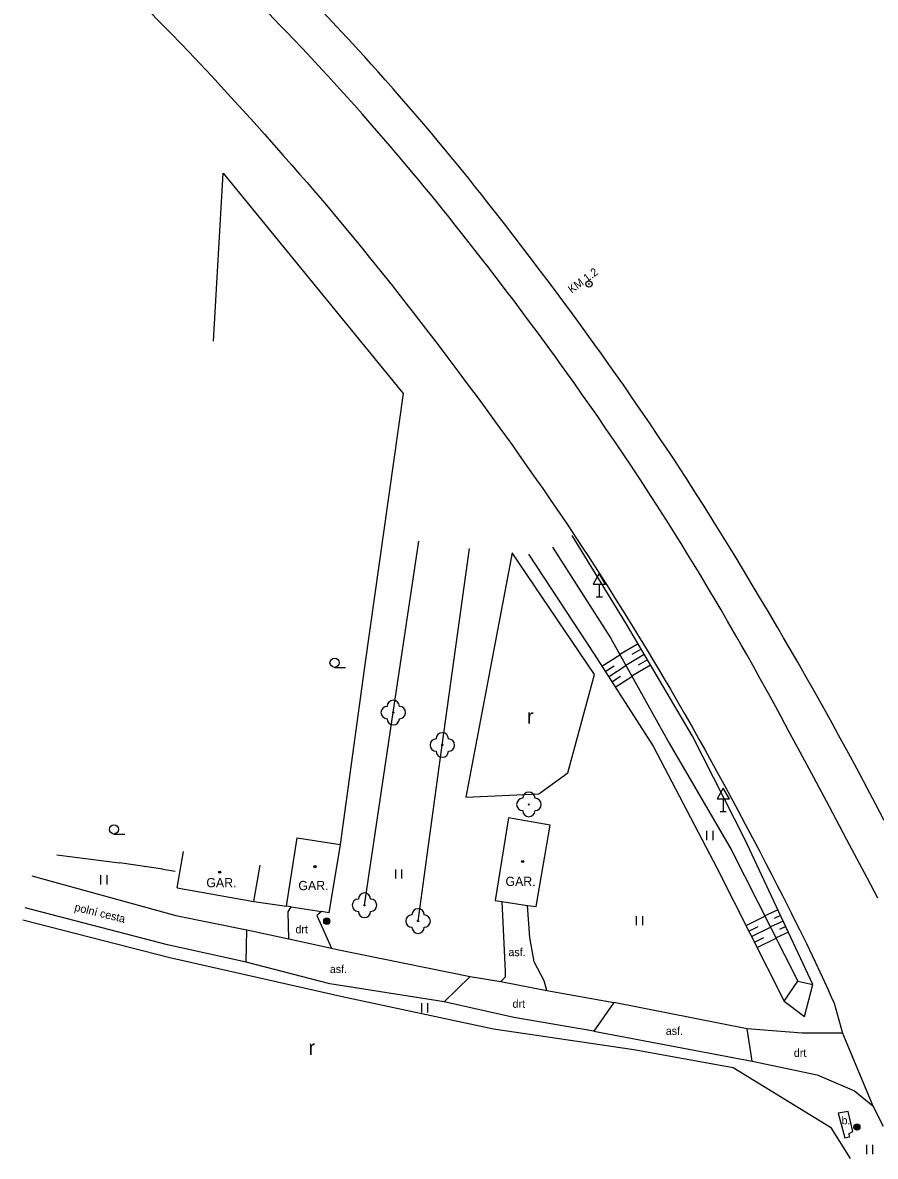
# Model space of a CAD drawing. Extents: x -539244 to -537359, y -1183785 to -1181851.
# Drawn here: x -538628.7 to -538559.5, y -1183406.5 to -1183314.4 of the extents above; entities that cross this region are included whole.
import ezdxf

# ---------------------------------------------------------------- set-up
doc = ezdxf.new("R2010")
doc.units = 0
for name, color, linetype in [('Vrstva 10', 7, 'Continuous'), ('Vrstva 11', 7, 'Continuous'), ('Vrstva 13', 7, 'Continuous'), ('Vrstva 14', 7, 'Continuous'), ('Vrstva 15', 7, 'Continuous'), ('Vrstva 21', 7, 'Continuous'), ('Vrstva 22', 7, 'Continuous'), ('Vrstva 23', 7, 'Continuous'), ('Vrstva 25', 7, 'Continuous'), ('Vrstva 34', 7, 'Continuous'), ('Vrstva 36', 7, 'Continuous'), ('Vrstva 39', 7, 'Continuous'), ('Vrstva 40', 7, 'Continuous'), ('Vrstva 41', 7, 'Continuous'), ('Vrstva 5', 7, 'Continuous'), ('Vrstva 6', 7, 'Continuous'), ('Vrstva 7', 7, 'Continuous'), ('Vrstva 8', 7, 'Continuous')]:
    doc.layers.add(name, color=color, linetype=linetype)

msp = doc.modelspace()

# ---------------------------------------------------------------- linework, layer by layer
at = {"layer": 'Vrstva 10'}
for p, q in [((-538600.501, -1183322.527), (-538601.165, -1183321.773)), ((-538609.088, -1183323.418), (-538608.299, -1183324.305)), ((-538602.366, -1183331.225), (-538601.676, -1183332.061)), ((-538586.793, -1183339.695), (-538587.56, -1183338.659)), ((-538595.932, -1183339.308), (-538594.993, -1183340.538)), ((-538580.591, -1183348.465), (-538581.331, -1183347.379)), ((-538575.254, -1183356.683), (-538575.765, -1183355.863)), ((-538572.192, -1183375.483), (-538571.651, -1183376.476)), ((-538563.219, -1183378.053), (-538564.475, -1183375.691)), ((-538567.032, -1183385.26), (-538566.647, -1183386.018)), ((-538562.16, -1183396.46), (-538559.68, -1183402.36)), ((-538559.68, -1183402.36), (-538558.86, -1183403.993))]:
    msp.add_line(p, q, dxfattribs=at)
for points in [[(-538607.834, -1183314.562), (-538608.751, -1183313.619), (-538609.443, -1183312.915), (-538609.964, -1183312.389), (-538610.75, -1183311.603), (-538611.54, -1183310.82), (-538612.321, -1183310.053), (-538613.079, -1183309.313), (-538613.815, -1183308.599), (-538614.53, -1183307.91)], [(-538621.887, -1183310.038), (-538621.344, -1183310.564), (-538620.837, -1183311.06), (-538619.891, -1183311.993), (-538619.066, -1183312.814), (-538618.348, -1183313.536), (-538617.722, -1183314.171), (-538617.176, -1183314.728), (-538616.7, -1183315.218), (-538615.869, -1183316.078), (-538615.249, -1183316.727)], [(-538601.165, -1183321.773), (-538601.79, -1183321.069), (-538602.378, -1183320.412), (-538602.933, -1183319.798), (-538603.455, -1183319.224), (-538603.946, -1183318.687), (-538604.408, -1183318.185), (-538605.279, -1183317.249), (-538606.045, -1183316.433), (-538606.72, -1183315.722), (-538607.313, -1183315.102), (-538607.834, -1183314.562)], [(-538615.249, -1183316.727), (-538614.322, -1183317.705), (-538613.4, -1183318.69), (-538612.858, -1183319.273), (-538611.814, -1183320.407), (-538610.84, -1183321.473), (-538609.933, -1183322.475), (-538609.088, -1183323.418)], [(-538594.637, -1183329.503), (-538595.133, -1183328.89), (-538595.617, -1183328.297), (-538596.086, -1183327.725), (-538596.543, -1183327.172), (-538596.987, -1183326.638), (-538597.418, -1183326.123), (-538598.258, -1183325.128), (-538599.05, -1183324.2), (-538599.797, -1183323.335), (-538600.501, -1183322.527)], [(-538608.299, -1183324.305), (-538607.563, -1183325.139), (-538606.877, -1183325.923), (-538606.236, -1183326.66), (-538605.637, -1183327.353), (-538605.078, -1183328.004), (-538604.556, -1183328.617), (-538604.068, -1183329.192), (-538603.158, -1183330.274), (-538602.366, -1183331.225)], [(-538588.828, -1183336.965), (-538589.35, -1183336.276), (-538590.268, -1183335.072), (-538590.96, -1183334.171), (-538591.482, -1183333.497), (-538592.269, -1183332.487), (-538593.06, -1183331.48), (-538593.6, -1183330.798), (-538594.126, -1183330.139), (-538594.637, -1183329.503)], [(-538601.676, -1183332.061), (-538601.076, -1183332.794), (-538600.552, -1183333.438), (-538600.095, -1183334.003), (-538599.3, -1183334.995), (-538598.706, -1183335.742), (-538598.263, -1183336.305), (-538597.6, -1183337.151), (-538596.94, -1183338), (-538595.932, -1183339.308)], [(-538587.56, -1183338.659), (-538588.234, -1183337.755), (-538588.828, -1183336.965)], [(-538581.331, -1183347.379), (-538582.03, -1183346.364), (-538582.689, -1183345.415), (-538583.311, -1183344.528), (-538583.898, -1183343.699), (-538584.45, -1183342.923), (-538584.971, -1183342.197), (-538585.461, -1183341.519), (-538585.923, -1183340.883), (-538586.793, -1183339.695)], [(-538594.993, -1183340.538), (-538594.118, -1183341.693), (-538593.302, -1183342.778), (-538592.541, -1183343.798), (-538591.831, -1183344.756), (-538591.169, -1183345.656), (-538590.551, -1183346.502), (-538589.974, -1183347.297), (-538589.436, -1183348.044)], [(-538589.436, -1183348.044), (-538588.933, -1183348.745), (-538588.464, -1183349.404)], [(-538575.765, -1183355.863), (-538576.264, -1183355.072), (-538576.749, -1183354.307), (-538577.222, -1183353.568), (-538577.682, -1183352.855), (-538578.131, -1183352.165), (-538578.567, -1183351.498), (-538578.992, -1183350.854), (-538579.405, -1183350.231), (-538579.807, -1183349.629), (-538580.591, -1183348.465)], [(-538588.464, -1183349.404), (-538588.026, -1183350.023), (-538587.209, -1183351.187), (-538586.499, -1183352.209), (-538585.881, -1183353.106), (-538585.343, -1183353.894), (-538584.875, -1183354.584), (-538584.467, -1183355.19), (-538583.758, -1183356.253), (-538583.229, -1183357.054), (-538582.834, -1183357.656)], [(-538570.382, -1183364.894), (-538570.781, -1183364.194), (-538571.485, -1183362.97), (-538572.017, -1183362.054), (-538572.419, -1183361.369), (-538573.027, -1183360.343), (-538573.64, -1183359.32), (-538574.192, -1183358.41), (-538574.73, -1183357.531), (-538575.254, -1183356.683)], [(-538582.834, -1183357.656), (-538582.245, -1183358.561), (-538581.66, -1183359.47), (-538581.27, -1183360.081), (-538580.52, -1183361.267), (-538579.823, -1183362.381), (-538579.176, -1183363.429), (-538578.574, -1183364.413), (-538578.014, -1183365.338)], [(-538568.827, -1183367.665), (-538569.413, -1183366.614), (-538569.928, -1183365.696), (-538570.382, -1183364.894)], [(-538578.014, -1183365.338), (-538577.492, -1183366.207), (-538577.006, -1183367.024)], [(-538577.006, -1183367.024), (-538576.553, -1183367.791), (-538576.131, -1183368.511), (-538575.738, -1183369.187), (-538575.005, -1183370.458), (-538574.369, -1183371.574), (-538573.816, -1183372.552), (-538573.336, -1183373.411), (-538572.918, -1183374.163), (-538572.192, -1183375.483)], [(-538564.475, -1183375.691), (-538565.579, -1183373.625), (-538566.551, -1183371.821), (-538567.408, -1183370.244), (-538568.162, -1183368.867), (-538568.827, -1183367.665)], [(-538571.651, -1183376.476), (-538571.248, -1183377.222), (-538570.647, -1183378.345), (-538570.05, -1183379.47), (-538568.876, -1183381.7), (-538568.366, -1183382.676), (-538567.89, -1183383.593), (-538567.446, -1183384.453), (-538567.032, -1183385.26)], [(-538559.27, -1183385.48), (-538560.147, -1183383.837), (-538561.786, -1183380.753), (-538563.219, -1183378.053)], [(-538566.647, -1183386.018), (-538566.288, -1183386.73), (-538565.954, -1183387.398), (-538565.643, -1183388.026), (-538565.354, -1183388.615), (-538565.084, -1183389.168), (-538564.834, -1183389.687), (-538564.369, -1183390.664), (-538563.967, -1183391.52), (-538563.621, -1183392.272), (-538563.322, -1183392.932), (-538563.063, -1183393.51), (-538562.839, -1183394.017), (-538562.16, -1183396.46)]]:
    msp.add_lwpolyline(points, dxfattribs=at)
at = {"layer": 'Vrstva 11'}
for p, q in [((-538628, -1183383.67), (-538616.28, -1183386.88)), ((-538616.96, -1183389.28), (-538628.54, -1183386.27)), ((-538616.28, -1183386.88), (-538610.53, -1183388.05)), ((-538610.58, -1183390.68), (-538616.96, -1183389.28)), ((-538603.65, -1183389.55), (-538603.18, -1183389.66)), ((-538603.18, -1183389.66), (-538592.39, -1183391.84)), ((-538603.79, -1183392.45), (-538610.58, -1183390.68)), ((-538594.49, -1183393.9), (-538603.79, -1183392.45)), ((-538586.16, -1183392.98), (-538580.71, -1183393.96)), ((-538588.83, -1183395.17), (-538594.49, -1183393.9)), ((-538580.71, -1183393.96), (-538582.34, -1183396.28)), ((-538569.9, -1183396.1), (-538580.71, -1183393.96)), ((-538582.34, -1183396.28), (-538588.83, -1183395.17)), ((-538569.48, -1183398.73), (-538569.9, -1183396.1)), ((-538582.34, -1183396.28), (-538569.48, -1183398.73)), ((-538569.48, -1183398.73), (-538564.21, -1183399.84))]:
    msp.add_line(p, q, dxfattribs=at)
for points in [[(-538589.82, -1183385.75), (-538589.65, -1183389.17), (-538589.55, -1183391.43), (-538589.55, -1183391.891), (-538589.9, -1183392.25)], [(-538586.16, -1183392.98), (-538586.37, -1183392.2), (-538587.19, -1183390.66), (-538587.53, -1183388.67), (-538587.74, -1183386.07)], [(-538607.12, -1183388.78), (-538607.16, -1183386.6), (-538606.92, -1183386.19)], [(-538604.46, -1183386.56), (-538604.83, -1183386.89), (-538603.65, -1183389.55)], [(-538610.58, -1183390.68), (-538610.53, -1183388.05), (-538607.12, -1183388.78), (-538603.65, -1183389.55)], [(-538594.49, -1183393.9), (-538592.39, -1183391.84), (-538589.9, -1183392.25), (-538586.16, -1183392.98)], [(-538562.16, -1183396.46), (-538565.43, -1183396.45), (-538569.9, -1183396.1)], [(-538564.21, -1183399.84), (-538561.18, -1183401.13), (-538559.68, -1183402.36)], [(-538562.5, -1183402.95), (-538561.95, -1183404.95), (-538561.57, -1183404.87), (-538561.61, -1183404.61), (-538561.3, -1183404.45), (-538561.68, -1183402.82), (-538562.5, -1183402.95)]]:
    msp.add_lwpolyline(points, dxfattribs=at)
at = {"layer": 'Vrstva 13'}
for p, q in [((-538598.626, -1183319.749), (-538599.261, -1183319.029)), ((-538591.999, -1183327.658), (-538592.503, -1183327.03)), ((-538585.543, -1183336.039), (-538586.141, -1183335.239)), ((-538579.282, -1183344.75), (-538579.948, -1183343.791)), ((-538573.449, -1183353.55), (-538573.94, -1183352.778))]:
    msp.add_line(p, q, dxfattribs=at)
for points in [[(-538599.261, -1183319.029), (-538599.859, -1183318.356), (-538600.422, -1183317.728), (-538600.952, -1183317.141), (-538601.451, -1183316.592), (-538601.921, -1183316.078), (-538602.806, -1183315.12), (-538603.585, -1183314.285), (-538604.27, -1183313.557), (-538604.873, -1183312.923), (-538605.403, -1183312.37), (-538605.868, -1183311.887)], [(-538592.503, -1183327.03), (-538592.994, -1183326.424), (-538593.47, -1183325.838), (-538593.934, -1183325.273), (-538594.384, -1183324.727), (-538594.822, -1183324.199), (-538595.674, -1183323.182), (-538596.479, -1183322.232), (-538597.237, -1183321.347), (-538597.952, -1183320.521), (-538598.626, -1183319.749)], [(-538586.141, -1183335.239), (-538586.666, -1183334.54), (-538587.591, -1183333.321), (-538588.288, -1183332.408), (-538588.813, -1183331.725), (-538589.604, -1183330.701), (-538590.4, -1183329.68), (-538590.948, -1183328.982), (-538591.481, -1183328.308), (-538591.999, -1183327.658)], [(-538579.948, -1183343.791), (-538580.577, -1183342.893), (-538581.169, -1183342.055), (-538581.727, -1183341.27), (-538582.252, -1183340.536), (-538582.747, -1183339.849), (-538583.212, -1183339.206), (-538584.09, -1183338.004), (-538584.863, -1183336.954), (-538585.543, -1183336.039)], [(-538573.94, -1183352.778), (-538574.419, -1183352.031), (-538574.885, -1183351.31), (-538575.339, -1183350.613), (-538575.78, -1183349.94), (-538576.21, -1183349.289), (-538576.628, -1183348.659), (-538577.035, -1183348.051), (-538577.827, -1183346.875), (-538578.576, -1183345.776), (-538579.282, -1183344.75)], [(-538568.249, -1183362.089), (-538568.879, -1183361.025), (-538569.831, -1183359.431), (-538570.79, -1183357.84), (-538571.349, -1183356.921), (-538571.894, -1183356.034), (-538572.426, -1183355.177), (-538572.944, -1183354.349), (-538573.449, -1183353.55)], [(-538563.435, -1183370.477), (-538563.88, -1183369.68), (-538564.299, -1183368.934), (-538565.089, -1183367.538), (-538565.786, -1183366.319), (-538566.399, -1183365.254), (-538566.939, -1183364.323), (-538567.414, -1183363.51), (-538568.249, -1183362.089)], [(-538558.768, -1183379.17), (-538559.474, -1183377.813), (-538560.141, -1183376.544), (-538560.772, -1183375.357), (-538561.368, -1183374.247), (-538561.931, -1183373.209), (-538562.462, -1183372.237), (-538562.963, -1183371.328), (-538563.435, -1183370.477)]]:
    msp.add_lwpolyline(points, dxfattribs=at)
at = {"layer": 'Vrstva 14'}
for p, q in [((-538579.7, -1183363.22), (-538584.1, -1183356.02)), ((-538587.66, -1183357.54), (-538582.32, -1183365.67)), ((-538585.7, -1183356.96), (-538581, -1183364.34)), ((-538574.33, -1183372.31), (-538579.7, -1183363.22)), ((-538581, -1183364.34), (-538576.23, -1183372.9)), ((-538582.32, -1183365.67), (-538577.53, -1183373.14)), ((-538577.53, -1183373.14), (-538572.35, -1183383.03)), ((-538576.23, -1183372.9), (-538571.19, -1183381.53)), ((-538570.07, -1183380.69), (-538574.33, -1183372.31)), ((-538564.55, -1183392.5), (-538570.07, -1183380.69)), ((-538571.19, -1183381.53), (-538565.77, -1183392.22)), ((-538572.35, -1183383.03), (-538566.89, -1183393.85))]:
    msp.add_line(p, q, dxfattribs=at)
for points in [[(-538566.89, -1183393.85), (-538565.77, -1183392.22), (-538564.55, -1183392.5)], [(-538566.89, -1183393.85), (-538565.23, -1183395.09), (-538564.55, -1183392.5)]]:
    msp.add_lwpolyline(points, dxfattribs=at)
at = {"layer": 'Vrstva 15'}
for p, q in [((-538578.756, -1183364.819), (-538580.243, -1183365.698)), ((-538581.693, -1183366.648), (-538580.235, -1183365.713)), ((-538578.247, -1183365.68), (-538579.757, -1183366.571)), ((-538578.501, -1183365.249), (-538579.251, -1183365.692)), ((-538581.423, -1183367.068), (-538580.707, -1183366.609)), ((-538581.153, -1183367.489), (-538579.747, -1183366.588)), ((-538577.738, -1183366.541), (-538579.27, -1183367.445)), ((-538577.993, -1183366.11), (-538578.742, -1183366.553)), ((-538580.883, -1183367.91), (-538580.167, -1183367.451)), ((-538580.614, -1183368.331), (-538579.26, -1183367.463)), ((-538569.986, -1183387.714), (-538568.448, -1183386.938)), ((-538567.387, -1183386.431), (-538568.453, -1183386.929)), ((-538567.175, -1183386.884), (-538567.701, -1183387.129)), ((-538569.761, -1183388.161), (-538568.991, -1183387.772)), ((-538569.536, -1183388.607), (-538567.996, -1183387.83)), ((-538566.963, -1183387.337), (-538568, -1183387.821)), ((-538566.752, -1183387.79), (-538567.277, -1183388.035)), ((-538569.31, -1183389.053), (-538568.541, -1183388.665)), ((-538569.085, -1183389.5), (-538567.544, -1183388.722)), ((-538566.54, -1183388.242), (-538567.548, -1183388.714))]:
    msp.add_line(p, q, dxfattribs=at)
at = {"layer": 'Vrstva 21'}
for p, q in [((-538598.63, -1183370.4), (-538596.549, -1183356.471)), ((-538594.65, -1183373.04), (-538592.452, -1183357.083)), ((-538600.97, -1183386.06), (-538598.63, -1183370.4)), ((-538596.62, -1183387.34), (-538594.65, -1183373.04))]:
    msp.add_line(p, q, dxfattribs=at)
at = {"layer": 'Vrstva 22'}
for centre in [(-538598.63, -1183370.4), (-538594.65, -1183373.04), (-538587.62, -1183377.87), (-538600.97, -1183386.06), (-538596.62, -1183387.34)]:
    msp.add_circle(centre, 0.05, dxfattribs=at)
for centre, start, end in [((-538598.63, -1183369.9), 0, 180), ((-538599.13, -1183370.4), 90, 270), ((-538598.13, -1183370.4), 270, 90), ((-538598.63, -1183370.9), 180, 0), ((-538594.65, -1183372.54), 0, 180), ((-538595.15, -1183373.04), 90, 270), ((-538594.15, -1183373.04), 270, 90), ((-538594.65, -1183373.54), 180, 0), ((-538587.62, -1183377.37), 0, 180), ((-538588.12, -1183377.87), 90, 270), ((-538587.12, -1183377.87), 270, 90), ((-538587.62, -1183378.37), 180, 0), ((-538600.97, -1183385.56), 0, 180), ((-538601.47, -1183386.06), 90, 270), ((-538600.47, -1183386.06), 270, 90), ((-538600.97, -1183386.56), 180, 0), ((-538597.12, -1183387.34), 90, 270), ((-538596.62, -1183386.84), 0, 180), ((-538596.12, -1183387.34), 270, 90), ((-538596.62, -1183387.84), 180, 0)]:
    msp.add_arc(centre, 0.5, start, end, dxfattribs=at)
at = {"layer": 'Vrstva 23'}
for p, q in [((-538588.97, -1183357.43), (-538592.73, -1183377.27)), ((-538582.3, -1183367.31), (-538588.97, -1183357.43)), ((-538584.47, -1183375.31), (-538582.3, -1183367.31)), ((-538586.81, -1183377), (-538584.47, -1183375.31)), ((-538592.73, -1183377.27), (-538586.81, -1183377)), ((-538628.73, -1183387.24), (-538616.78, -1183390.29)), ((-538616.78, -1183390.29), (-538602.66, -1183393.5)), ((-538602.66, -1183393.5), (-538590.49, -1183396.09)), ((-538590.49, -1183396.09), (-538579.1, -1183397.78)), ((-538579.1, -1183397.78), (-538571.04, -1183399.25)), ((-538571.04, -1183399.25), (-538563.13, -1183404.09)), ((-538563.13, -1183404.09), (-538561.52, -1183406.64))]:
    msp.add_line(p, q, dxfattribs=at)
at = {"layer": 'Vrstva 25'}
for centre, radius in [((-538582.74, -1183335.59), 0.25), ((-538582.74, -1183335.59), 0.0303), ((-538604.03, -1183387.35), 0.25), ((-538604.03, -1183387.35), 0.2), ((-538604.03, -1183387.35), 0.15), ((-538604.03, -1183387.35), 0.1), ((-538604.03, -1183387.35), 0.05), ((-538560.98, -1183404.08), 0.25), ((-538560.98, -1183404.08), 0.2), ((-538560.98, -1183404.08), 0.15), ((-538560.98, -1183404.08), 0.1), ((-538560.98, -1183404.08), 0.05)]:
    msp.add_circle(centre, radius, dxfattribs=at)
at = {"layer": 'Vrstva 34'}
for p, q in [((-538581.9, -1183359.974), (-538581.9, -1183360.99)), ((-538582.15, -1183360.99), (-538581.65, -1183360.99)), ((-538571.84, -1183377.414), (-538571.84, -1183378.43)), ((-538572.09, -1183378.43), (-538571.59, -1183378.43))]:
    msp.add_line(p, q, dxfattribs=at)
for points in [[(-538582.4, -1183359.974), (-538581.4, -1183359.974), (-538581.9, -1183359.106)], [(-538572.34, -1183377.414), (-538571.34, -1183377.414), (-538571.84, -1183376.546)]]:
    msp.add_lwpolyline(points, close=True, dxfattribs=at)
at = {"layer": 'Vrstva 36'}
for p, q in [((-538603.398, -1183366.731), (-538602.523, -1183366.731)), ((-538621.315, -1183380.27), (-538620.44, -1183380.27)), ((-538573.16, -1183380.774), (-538573.16, -1183380.024)), ((-538572.659, -1183380.774), (-538572.659, -1183380.024)), ((-538598.436, -1183383.893), (-538598.436, -1183383.143)), ((-538597.935, -1183383.893), (-538597.935, -1183383.143)), ((-538622.371, -1183384.372), (-538622.371, -1183383.622)), ((-538621.87, -1183384.372), (-538621.87, -1183383.622)), ((-538578.876, -1183387.681), (-538578.876, -1183386.931)), ((-538578.375, -1183387.681), (-538578.375, -1183386.931)), ((-538596.325, -1183394.757), (-538596.325, -1183394.007)), ((-538595.824, -1183394.757), (-538595.824, -1183394.007)), ((-538560.185, -1183406.267), (-538560.185, -1183405.517)), ((-538559.684, -1183406.267), (-538559.684, -1183405.517))]:
    msp.add_line(p, q, dxfattribs=at)
for centre in [(-538603.398, -1183366.356), (-538621.315, -1183379.895)]:
    msp.add_circle(centre, 0.375, dxfattribs=at)
at = {"layer": 'Vrstva 39'}
for centre, radius in [((-538588.122, -1183382.506), 0.09), ((-538612.728, -1183383.371), 0.09), ((-538612.728, -1183383.371), 0.0398), ((-538604.992, -1183382.919), 0.09), ((-538604.992, -1183382.919), 0.0398), ((-538588.122, -1183382.506), 0.0398)]:
    msp.add_circle(centre, radius, dxfattribs=at)
at = {"layer": 'Vrstva 5'}
for p, q in [((-538589.27, -1183378.96), (-538590.37, -1183385.67)), ((-538585.9, -1183379.55), (-538589.27, -1183378.96)), ((-538587.04, -1183386.17), (-538585.9, -1183379.55)), ((-538607.31, -1183386.13), (-538606.45, -1183380.567)), ((-538606.45, -1183380.567), (-538602.94, -1183381.11)), ((-538602.94, -1183381.11), (-538603.88, -1183386.66)), ((-538616.19, -1183384.65), (-538615.668, -1183381.696)), ((-538609.96, -1183385.75), (-538609.438, -1183382.796)), ((-538616.19, -1183384.65), (-538609.96, -1183385.75)), ((-538590.37, -1183385.67), (-538589.82, -1183385.75)), ((-538589.82, -1183385.75), (-538587.74, -1183386.07)), ((-538587.74, -1183386.07), (-538587.04, -1183386.17)), ((-538606.92, -1183386.19), (-538607.31, -1183386.13)), ((-538603.88, -1183386.66), (-538604.46, -1183386.56))]:
    msp.add_line(p, q, dxfattribs=at)
at = {"layer": 'Vrstva 6'}
msp.add_line((-538606.92, -1183386.19), (-538604.46, -1183386.56), dxfattribs=at)
at = {"layer": 'Vrstva 7'}
for p, q in [((-538613.22, -1183340.237), (-538612.44, -1183326.58)), ((-538612.44, -1183326.58), (-538597.82, -1183344.49)), ((-538597.82, -1183344.49), (-538600.93, -1183366.51)), ((-538600.93, -1183366.51), (-538602.94, -1183381.11)), ((-538617.36, -1183383.13), (-538620.86, -1183382.61))]:
    msp.add_line(p, q, dxfattribs=at)
at = {"layer": 'Vrstva 8'}
for p, q in [((-538625.95, -1183381.96), (-538620.86, -1183382.61)), ((-538617.36, -1183383.13), (-538616.35, -1183383.28)), ((-538609.96, -1183385.75), (-538607.31, -1183386.13))]:
    msp.add_line(p, q, dxfattribs=at)

# ---------------------------------------------------------------- texts
at = {"layer": 'Vrstva 36'}
for p in [(-538587.777, -1183371.317), (-538605.518, -1183398.215)]:
    msp.add_text('r', height=1.2, dxfattribs=at).set_placement(p)
at = {"layer": 'Vrstva 40'}
for s, rotation, p in [('KM 1.2', 36.43552, (-538584.146, -1183336.38)), ('polní cesta', 346.18457, (-538624.566, -1183386.492))]:
    msp.add_text(s, height=0.65, rotation=rotation, dxfattribs=at).set_placement(p)
for s, p in [('drt', (-538606.579, -1183388.334)), ('asf.', (-538589.284, -1183390.193)), ('asf.', (-538603.787, -1183391.563)), ('drt', (-538588.946, -1183394.386)), ('asf.', (-538576.503, -1183396.588)), ('drt', (-538566.103, -1183398.375)), ('b.', (-538562.233, -1183403.851))]:
    msp.add_text(s, height=0.65, dxfattribs=at).set_placement(p)
at = {"layer": 'Vrstva 41'}
for p in [(-538613.816, -1183384.596), (-538606.344, -1183384.83), (-538589.522, -1183384.492)]:
    msp.add_text('GAR.', height=0.75, dxfattribs=at).set_placement(p)

doc.saveas('drawing.dxf')
